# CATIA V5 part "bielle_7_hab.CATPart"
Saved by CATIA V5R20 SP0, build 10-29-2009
Part number: bielle_7_hab
Bounding box of the stored display mesh (mm): x 0 to 0.05, y -0.1 to 2.18, z -1.1 to 1.27
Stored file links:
  D:\Dropbox\IAO_2012\IAO_2012_718_ccascaro\ccascaro\bielle_7_hab.CATPart
  D:\Dropbox\IAO_2012\IAO_2012_718_ccascaro\ccascaro\ccascaro.CATProduct
  D:\Dropbox\IAO_2012\IAO_2012_718_ccascaro\ccascaro\Part15.CATPart
  D:\Dropbox\IAO_2012\IAO_2012_718_ccascaro\ccascaro\bielle_3_hab.CATPart
  D:\Dropbox\IAO_2012\IAO_2012_718_ccascaro\ccascaro\Part14.CATPart
  D:\Dropbox\IAO_2012\IAO_2012_718_ccascaro\ccascaro\bielle_5_hab.CATPart
  D:\Dropbox\IAO_2012\IAO_2012_718_ccascaro\ccascaro\bielle_6_hab.CATPart
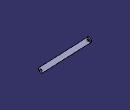
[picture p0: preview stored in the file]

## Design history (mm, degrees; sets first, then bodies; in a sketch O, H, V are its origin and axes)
Set1
  Plane1: linked copy from another document
  Point1 "point H": linked copy from another document
  Point2 "point D": linked copy from another document
  Point3 "point G": linked copy from another document
  DatumCurve1: linked copy from another document
Body1 (main body)
  Sketch1 on yz-plane, origin (0, 0, 0), H (0, 1, 0), V (0, 0, 1)
    construction line L1 (0, -1) -> (2.08, 1.17)
    point P1 (0, -1)
    point P2 (2.08, 1.17)
    line L2 (-0.0722, -0.9308) -> (2.0078, 1.2392)
    line L3 (2.1522, 1.1008) -> (0.0722, -1.0692)
    arc A1 centre (2.08, 1.17) radius 0.1 from (2.0078, 1.2392) to (2.1522, 1.1008) cw
    arc A2 centre (0, -1) radius 0.1 from (0.0722, -1.0692) to (-0.0722, -0.9308) cw
    reference projected point E1 (2.08, 1.17) from Point3
    reference projected point E2 (0, -1) from Point1
    circle A3 centre (2.08, 1.17) radius 0.05
    reference projected circle E3 centre (2.08, 1.17) radius 0.05 from edge of DatumCurve1
    circle A4 centre (0, -1) radius 0.05
    radius A2 = 0.1
    tangency: A1 L2, A2 L2, A1 L3, A2 L3
    coincidence: P2 E1, P1 E2
    concentricity: A3 E3, A4 A2
  Pad1: profile Sketch1, direction (1, 0, 0), length 0.05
